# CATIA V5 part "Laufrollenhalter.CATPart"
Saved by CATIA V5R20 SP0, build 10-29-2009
Part number: Laufrollenhalter
Bounding box of the stored display mesh (mm): x -20 to 20, y -20 to 20, z 0 to 12
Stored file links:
  C:\Users\Andi\Desktop\Plasma\Laufrollenhalter.CATPart
  C:\Program Files\Dassault Systemes\B20\win_b64\reffiles\standard\MetricThickPitch.txt
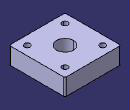
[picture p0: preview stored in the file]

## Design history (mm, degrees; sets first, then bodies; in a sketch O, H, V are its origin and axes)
Body1 (main body)
  Sketch1 on xy-plane, origin (0, 0, 0), H (1, 0, 0), V (0, 1, 0)
    line L1 (20, 20) -> (20, -20)
    line L2 (20, -20) -> (-20, -20)
    line L3 (-20, -20) -> (-20, 20)
    line L4 (-20, 20) -> (20, 20)
    circle A1 centre (0, 0) radius 6
    distance L2 L4 = 40
    distance L1 L3 = 40
    radius A1 = 6
    vertical: L1 V, L3 V
    horizontal: L2 H, L4 H
    equidistance: L1 L3 O, L2 L4 O
  Pad1: profile Sketch1, direction (0, 0, 1), length 12
  Sketch2 on end face of Pad1, origin (-13.1073, -13.6147, 12), H (1, 0, 0), V (0, 1, 0)
    point P1 (-0.3927, 27.1147)
    reference intersected line E1 through (13.1073, 0) direction (0, 1) from yz-plane
    reference intersected line E2 through (0, 13.6147) direction (-1, 0) from zx-plane
    distance P1 E1 = 13.5
    distance P1 E2 = 13.5 {= Sketch2.distance(P1 E1)}
  Hole1: placed by Sketch2, at (-13.5, 13.5, 12) direction (0, 0, -1), diameter 4.134, through (limit type 6), threaded "M5", thread diameter 5, thread depth 12, pitch 0.8
  CircPattern1: of Hole1, instances 4, angular step 90 {= 360.0*1 deg/CircPattern1.AngularNumber}, axis from face of Pad1 from Sketch1.A1
  Fillet1: radius 1, on edge [face of Pad1 from Sketch1.L1 | face of Pad1 from Sketch1.L2]; edge [face of Pad1 from Sketch1.L4 | face of Pad1 from Sketch1.L1]; edge [face of Pad1 from Sketch1.L3 | face of Pad1 from Sketch1.L4]; edge [face of Pad1 from Sketch1.L2 | face of Pad1 from Sketch1.L3]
